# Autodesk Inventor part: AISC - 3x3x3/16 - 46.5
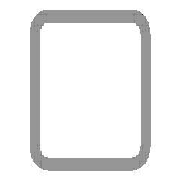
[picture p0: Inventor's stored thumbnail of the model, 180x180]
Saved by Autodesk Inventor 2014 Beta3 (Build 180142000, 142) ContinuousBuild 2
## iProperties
_CCFamilyMember: 9
_CCFamilyDisplayName: ANSI AISC (Square) - Tube
_FrameMemberDoc: Frame Member File
_Version: 15.0.0
_GetPNFromCC: 1
Created: 2011-01
Part Number: AISC - 3x3x3/16 - 46.5
Material: Steel, Mild
Description: Tube
Document SubType Name: Modeling
Standard: ANSI
Designer: Beta-8540w
Standards Organization: ANSI
Language: en-US
Size Designation: 3x3x3/16
Categories: <MemberInstance><Categories><Category DisplayName="Structural Shapes" InternalName="089c4875-fa83-4c05-b084-43b9cc11f5ed" Mnemonic="GRDR"><CategoryParameter Dis
Stock Number: 3x3x3/16
Density: 7.86 g/cm^3
Appearance: Steel
IsCustomPart: 1
G_W: 3.000 in
G_H: 3.000 in
G_L: 46.500 in
+284DB9ED-C03F-4F79-A74F-9B1518562CF0+CUTDETAIL2: Notch
Author: Beta-8540w
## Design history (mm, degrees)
node "Start plane"
node "End plane"
sketch "Sketch"
  geometry: L1 (-38.1, -28.575)-(-38.1, 28.575); L2 (-28.575, 38.1)-(28.575, 38.1); L3 (38.1, 28.575)-(38.1, -28.575); L4 (28.575, -38.1)-(-28.575, -38.1); L5 (-28.575, 33.337)-(28.575, 33.338); L6 (33.338, 28.575)-(33.338, -28.575); L7 (28.575, -33.337)-(-28.575, -33.338); L8 (-33.338, -28.575)-(-33.338, 28.575); L9 (0, 56.102)-(0, -56.102) reference; L10 (-56.102, 0)-(56.102, 0) reference; A1 r 9.525 centre (-28.575, -28.575) between (-38.1, -28.575) and (-28.575, -38.1); A2 r 9.525 centre (-28.575, 28.575) between (-28.575, 38.1) and (-38.1, 28.575); A3 r 9.525 centre (28.575, 28.575) between (38.1, 28.575) and (28.575, 38.1); A4 r 9.525 centre (28.575, -28.575) between (28.575, -38.1) and (38.1, -28.575); A5 r 4.763 centre (-28.575, 28.575) between (-28.575, 33.337) and (-33.338, 28.575); A6 r 4.763 centre (28.575, 28.575) between (33.338, 28.575) and (28.575, 33.338); A7 r 4.763 centre (28.575, -28.575) between (28.575, -33.337) and (33.338, -28.575); A8 r 4.763 centre (-28.575, -28.575) between (-33.338, -28.575) and (-28.575, -33.338)
  constraints: 16 end point, 16 point on circle, 8 centre point, 8 tangent, 4 parallel, 3 equal radius, 2 perpendicular, 7 other
  dimensions: "d10" = 76.2 distance between parallel lines of L2 L4 (= G_H); "d11" = 76.2 distance between parallel lines of L1 L3 (= G_W); "d12" = 4.7625 distance between parallel lines of L3 L6 (= G_T); "d15" = 38.1 distance between parallel lines of L2 L10 (= 0.5 x d10); "d16" = 38.1 distance between parallel lines of L9 L3 (= 0.5 x d11); "d17" = 9.525 radius of A1 (= G_IR)
extrude "Body" new body sketch "Sketch" stored distance "d3" = 1181.1 (= G_L); taper "d4" = 0 deg
node "Driven Length"
  sketch "Sketch3"
    geometry: L1 (0, 0)-(10, 0) reference
    constraints: 2 end point, 1 horizontal
  workplane "Work Plane3"
  sketch "Sketch4"
    geometry: L1 (-2, 38.1)-(12, 38.1) reference; L2 (-2, 1219.2)-(12, 1219.2) reference
    dimensions: "d19" = 1181.1 distance between parallel lines of L1 L2 (derived)
workplane "Work Plane4"
split "Split1"
body "Solid1"
feature "Sculpt1"
combine "Combine1"
body "Srf11"
body "Srf12"
body "Solid5"
feature "Surface1"
body "Srf10"
patch "Boundary Patch7" dims "d76" = 5, "d77" = 5, "d78" = 5, "d79" = 5, "d80" = 5, "d81" = 5, "d82" = 5, "d83" = 5, "d84" = 0
patch "Boundary Patch8" dims "d85" = 5, "d86" = 5, "d87" = 5, "d88" = 5, "d89" = 5, "d90" = 5, "d91" = 5, "d92" = 5, "d93" = 0
other parameters: "G_W" = 76.2 [user parameter; used in 1 equation term], "G_H" = 76.2 [user parameter; used in 1 equation term], "G_T" = 4.7625 [user parameter; used in 1 equation term], "G_IR" = 9.525 [user parameter; used in 1 equation term], "G_L" = 1181.1 (= d19) [user parameter; used in 1 equation term], "G_OFFSET_START" = -38.1 [user parameter; used in 1 equation term], "G_OFFSET_END" = 0 [user parameter; used in 1 equation term], "d13" = 38.1 (= -G_OFFSET_START), "d14" = 1219.2 (= G_OFFSET_END + B_L), "B_L" = 1219.2 [user parameter; used in 1 equation term], "d18" = 90 deg
